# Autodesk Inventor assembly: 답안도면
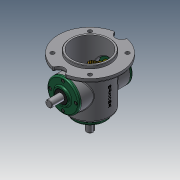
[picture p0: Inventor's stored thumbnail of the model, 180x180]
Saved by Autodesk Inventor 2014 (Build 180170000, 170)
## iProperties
Created: 2018-04
Part Number: 답안도면
Document SubType Name: Assembly
Designer: NET
Author: NET
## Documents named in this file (16)
- C:\Users\NET\Desktop\480407V1003\답안도면.iam
- C:\Users\NET\Desktop\480407V1003\본체.ipt
- C:\Users\NET\Desktop\480407V1003\메인 축.ipt
- 메인 축.ipt
- C:\Users\NET\Desktop\480407V1003\베어링 6203.ipt
- C:\Users\NET\Desktop\480407V1003\커버.ipt
- C:\Users\NET\Desktop\480407V1003\오일 실.ipt
- 오일 실.ipt
- C:\Users\NET\Desktop\480407V1003\메인 베벨기어.ipt
- C:\Users\NET\Desktop\480407V1003\키 5x5.ipt
- C:\Users\NET\Desktop\480407V1003\볼트 M4.ipt
- 볼트 M4.ipt
- C:\Users\NET\Desktop\480407V1003\서브 축.ipt
- 서브 축.ipt
- C:\Users\NET\Desktop\480407V1003\서브 베벨기어.ipt
- C:\Users\NET\Desktop\480407V1003\키 4x4.ipt
